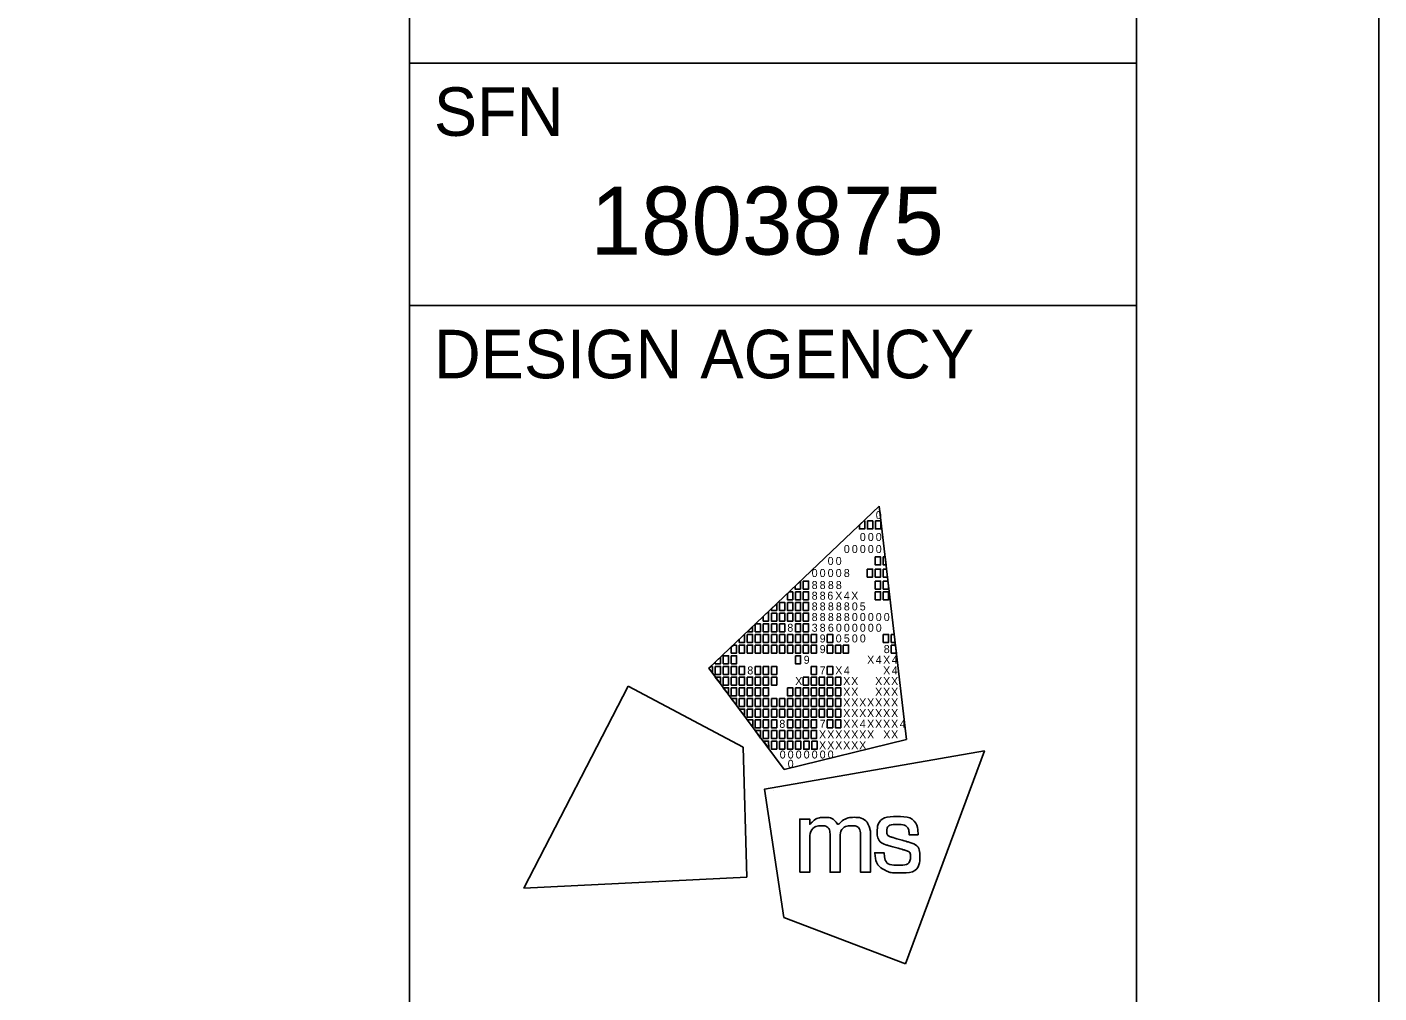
# Model space of a CAD drawing. Extents: x 0 to 34, y 0 to 22.
# Drawn here: x 31.211 to 34, y 3.582 to 5.574 of the extents above; entities that cross this region are included whole.
import ezdxf

# ---------------------------------------------------------------- set-up
doc = ezdxf.new("R2010")
doc.units = 0
for name, color, linetype in [('Default', 7, 'Continuous'), ('SH_Border', 7, 'Continuous'), ('SH_Cut_Line', 7, 'Continuous'), ('SH_Data', 7, 'Continuous')]:
    doc.layers.add(name, color=color, linetype=linetype)

msp = doc.modelspace()

# ---------------------------------------------------------------- linework, layer by layer
at = {"layer": 'Default'}
for p, q in [((32.6176, 4.2519), (32.9688, 4.5861)), ((32.9688, 4.5861), (32.9688, 4.5861)), ((32.9688, 4.5861), (33.0253, 4.1052)), ((32.773, 4.043), (32.6176, 4.2519)), ((33.0253, 4.1052), (32.773, 4.043))]:
    msp.add_line(p, q, dxfattribs=at)
for points in [[(32.9279, 4.5472), (32.9369, 4.5558), (32.939, 4.5558), (32.939, 4.5393), (32.9279, 4.5393)], [(32.9444, 4.5558), (32.9554, 4.5558), (32.9554, 4.5393), (32.9444, 4.5393)], [(32.9609, 4.5558), (32.9719, 4.5558), (32.9719, 4.5393), (32.9609, 4.5393)], [(32.9606, 4.4815), (32.9716, 4.4815), (32.9716, 4.465), (32.9606, 4.465)], [(32.9771, 4.4815), (32.9811, 4.4815), (32.983, 4.465), (32.9771, 4.465)], [(32.9442, 4.4567), (32.9552, 4.4567), (32.9552, 4.4402), (32.9442, 4.4402)], [(32.9606, 4.4567), (32.9716, 4.4567), (32.9716, 4.4402), (32.9606, 4.4402)], [(32.9771, 4.4567), (32.984, 4.4567), (32.9859, 4.4402), (32.9771, 4.4402)], [(32.7954, 4.4211), (32.8064, 4.4316), (32.8064, 4.4154), (32.7954, 4.4154)], [(32.7958, 4.4099), (32.8068, 4.4099), (32.8068, 4.3934), (32.7958, 4.3934)], [(32.8123, 4.4319), (32.8233, 4.4319), (32.8233, 4.4154), (32.8123, 4.4154)], [(32.8123, 4.4099), (32.8233, 4.4099), (32.8233, 4.3934), (32.8123, 4.3934)], [(32.9606, 4.4319), (32.9716, 4.4319), (32.9716, 4.4154), (32.9606, 4.4154)], [(32.9606, 4.4099), (32.9716, 4.4099), (32.9716, 4.3934), (32.9606, 4.3934)], [(32.9771, 4.4319), (32.9869, 4.4319), (32.9881, 4.4218), (32.9881, 4.4154), (32.9771, 4.4154)], [(32.9771, 4.4099), (32.9881, 4.4099), (32.9881, 4.3934), (32.9771, 4.3934)], [(32.7628, 4.3879), (32.7738, 4.3879), (32.7738, 4.3714), (32.7628, 4.3714)], [(32.7793, 4.3879), (32.7903, 4.3879), (32.7903, 4.3714), (32.7793, 4.3714)], [(32.7958, 4.3879), (32.8068, 4.3879), (32.8068, 4.3714), (32.7958, 4.3714)], [(32.8123, 4.3879), (32.8233, 4.3879), (32.8233, 4.3714), (32.8123, 4.3714)], [(32.7463, 4.3659), (32.7573, 4.3659), (32.7573, 4.3494), (32.7463, 4.3494)], [(32.7628, 4.3659), (32.7738, 4.3659), (32.7738, 4.3494), (32.7628, 4.3494)], [(32.7793, 4.3659), (32.7903, 4.3659), (32.7903, 4.3494), (32.7793, 4.3494)], [(32.7958, 4.3659), (32.8068, 4.3659), (32.8068, 4.3494), (32.7958, 4.3494)], [(32.8123, 4.3659), (32.8233, 4.3659), (32.8233, 4.3494), (32.8123, 4.3494)], [(32.7297, 4.3439), (32.7407, 4.3439), (32.7407, 4.3273), (32.7297, 4.3273)], [(32.7463, 4.3439), (32.7573, 4.3439), (32.7573, 4.3273), (32.7463, 4.3273)], [(32.7628, 4.3439), (32.7738, 4.3439), (32.7738, 4.3273), (32.7628, 4.3273)], [(32.7958, 4.3439), (32.8068, 4.3439), (32.8068, 4.3273), (32.7958, 4.3273)], [(32.8123, 4.3439), (32.8233, 4.3439), (32.8233, 4.3273), (32.8123, 4.3273)], [(32.6802, 4.2998), (32.6912, 4.2998), (32.6912, 4.2833), (32.6802, 4.2833)], [(32.6967, 4.3218), (32.7077, 4.3218), (32.7077, 4.3053), (32.6967, 4.3053)], [(32.6967, 4.2998), (32.7077, 4.2998), (32.7077, 4.2833), (32.6967, 4.2833)], [(32.7132, 4.3218), (32.7242, 4.3218), (32.7242, 4.3053), (32.7132, 4.3053)], [(32.7132, 4.2998), (32.7242, 4.2998), (32.7242, 4.2833), (32.7132, 4.2833)], [(32.7297, 4.3218), (32.7407, 4.3218), (32.7407, 4.3053), (32.7297, 4.3053)], [(32.7297, 4.2998), (32.7407, 4.2998), (32.7407, 4.2833), (32.7297, 4.2833)], [(32.7463, 4.3218), (32.7573, 4.3218), (32.7573, 4.3053), (32.7463, 4.3053)], [(32.7463, 4.2998), (32.7573, 4.2998), (32.7573, 4.2833), (32.7463, 4.2833)], [(32.7628, 4.3218), (32.7738, 4.3218), (32.7738, 4.3053), (32.7628, 4.3053)], [(32.7628, 4.2998), (32.7738, 4.2998), (32.7738, 4.2833), (32.7628, 4.2833)], [(32.7793, 4.3218), (32.7903, 4.3218), (32.7903, 4.3053), (32.7793, 4.3053)], [(32.7793, 4.2998), (32.7903, 4.2998), (32.7903, 4.2833), (32.7793, 4.2833)], [(32.7958, 4.3218), (32.8068, 4.3218), (32.8068, 4.3053), (32.7958, 4.3053)], [(32.7958, 4.2998), (32.8068, 4.2998), (32.8068, 4.2833), (32.7958, 4.2833)], [(32.8123, 4.3218), (32.8233, 4.3218), (32.8233, 4.3053), (32.8123, 4.3053)], [(32.8123, 4.2998), (32.8233, 4.2998), (32.8233, 4.2833), (32.8123, 4.2833)], [(32.8288, 4.3218), (32.8398, 4.3218), (32.8398, 4.3053), (32.8288, 4.3053)], [(32.8288, 4.2998), (32.8398, 4.2998), (32.8398, 4.2833), (32.8288, 4.2833)], [(32.8618, 4.3218), (32.8729, 4.3218), (32.8729, 4.3053), (32.8618, 4.3053)], [(32.8618, 4.2998), (32.8729, 4.2998), (32.8729, 4.2833), (32.8618, 4.2833)], [(32.8784, 4.2998), (32.8894, 4.2998), (32.8894, 4.2833), (32.8784, 4.2833)], [(32.8947, 4.2998), (32.9057, 4.2998), (32.9057, 4.2833), (32.8947, 4.2833)], [(32.9771, 4.3218), (32.9881, 4.3218), (32.9881, 4.3053), (32.9771, 4.3053)], [(32.9936, 4.3218), (32.9999, 4.3218), (33.0018, 4.3053), (32.9936, 4.3053)], [(32.9936, 4.2998), (33.0024, 4.2998), (33.0044, 4.2833), (32.9936, 4.2833)], [(32.6472, 4.2778), (32.6582, 4.2778), (32.6582, 4.2613), (32.6472, 4.2613)], [(32.6637, 4.2778), (32.6747, 4.2778), (32.6747, 4.2613), (32.6637, 4.2613)], [(32.7958, 4.2778), (32.8068, 4.2778), (32.8068, 4.2613), (32.7958, 4.2613)], [(32.6307, 4.2558), (32.6417, 4.2558), (32.6417, 4.2393), (32.6307, 4.2393)], [(32.6472, 4.2558), (32.6582, 4.2558), (32.6582, 4.2393), (32.6472, 4.2393)], [(32.6637, 4.2558), (32.6747, 4.2558), (32.6747, 4.2393), (32.6637, 4.2393)], [(32.6802, 4.2558), (32.6912, 4.2558), (32.6912, 4.2393), (32.6802, 4.2393)], [(32.7132, 4.2558), (32.7242, 4.2558), (32.7242, 4.2393), (32.7132, 4.2393)], [(32.7297, 4.2558), (32.7407, 4.2558), (32.7407, 4.2393), (32.7297, 4.2393)], [(32.7463, 4.2558), (32.7573, 4.2558), (32.7573, 4.2393), (32.7463, 4.2393)], [(32.8288, 4.2558), (32.8398, 4.2558), (32.8398, 4.2393), (32.8288, 4.2393)], [(32.8618, 4.2558), (32.8729, 4.2558), (32.8729, 4.2393), (32.8618, 4.2393)], [(32.6307, 4.2338), (32.6417, 4.2338), (32.6417, 4.22)], [(32.6472, 4.2338), (32.6582, 4.2338), (32.6582, 4.2173), (32.6472, 4.2173)], [(32.6637, 4.2338), (32.6747, 4.2338), (32.6747, 4.2173), (32.6637, 4.2173)], [(32.6802, 4.2338), (32.6912, 4.2338), (32.6912, 4.2173), (32.6802, 4.2173)], [(32.6967, 4.2338), (32.7077, 4.2338), (32.7077, 4.2173), (32.6967, 4.2173)], [(32.7132, 4.2338), (32.7242, 4.2338), (32.7242, 4.2173), (32.7132, 4.2173)], [(32.7297, 4.2338), (32.7407, 4.2338), (32.7407, 4.2173), (32.7297, 4.2173)], [(32.7463, 4.2338), (32.7573, 4.2338), (32.7573, 4.2173), (32.7463, 4.2173)], [(32.8123, 4.2338), (32.8233, 4.2338), (32.8233, 4.2173), (32.8123, 4.2173)], [(32.8288, 4.2338), (32.8398, 4.2338), (32.8398, 4.2173), (32.8288, 4.2173)], [(32.8453, 4.2338), (32.8563, 4.2338), (32.8563, 4.2173), (32.8453, 4.2173)], [(32.8618, 4.2338), (32.8729, 4.2338), (32.8729, 4.2173), (32.8618, 4.2173)], [(32.8784, 4.2338), (32.8894, 4.2338), (32.8894, 4.2173), (32.8784, 4.2173)], [(32.6472, 4.2117), (32.6582, 4.2117), (32.6582, 4.198)], [(32.6637, 4.2117), (32.6747, 4.2117), (32.6747, 4.1952), (32.6637, 4.1952)], [(32.6637, 4.1897), (32.6747, 4.1897), (32.6747, 4.176)], [(32.6747, 4.1897), (32.6747, 4.1897), (32.6747, 4.1897)], [(32.6802, 4.2117), (32.6912, 4.2117), (32.6912, 4.1952), (32.6802, 4.1952)], [(32.6802, 4.1897), (32.6912, 4.1897), (32.6912, 4.1732), (32.6802, 4.1732)], [(32.6967, 4.2117), (32.7077, 4.2117), (32.7077, 4.1952), (32.6967, 4.1952)], [(32.6967, 4.1897), (32.7077, 4.1897), (32.7077, 4.1732), (32.6967, 4.1732)], [(32.7132, 4.2117), (32.7242, 4.2117), (32.7242, 4.1952), (32.7132, 4.1952)], [(32.7132, 4.1897), (32.7242, 4.1897), (32.7242, 4.1732), (32.7132, 4.1732)], [(32.7297, 4.2117), (32.7407, 4.2117), (32.7407, 4.1952), (32.7297, 4.1952)], [(32.7297, 4.1897), (32.7407, 4.1897), (32.7407, 4.1732), (32.7297, 4.1732)], [(32.7463, 4.1897), (32.7573, 4.1897), (32.7573, 4.1732), (32.7463, 4.1732)], [(32.7628, 4.1897), (32.7738, 4.1897), (32.7738, 4.1732), (32.7628, 4.1732)], [(32.7793, 4.2117), (32.7903, 4.2117), (32.7903, 4.1952), (32.7793, 4.1952)], [(32.7793, 4.1897), (32.7903, 4.1897), (32.7903, 4.1732), (32.7793, 4.1732)], [(32.7958, 4.2117), (32.8068, 4.2117), (32.8068, 4.1952), (32.7958, 4.1952)], [(32.7958, 4.1897), (32.8068, 4.1897), (32.8068, 4.1732), (32.7958, 4.1732)], [(32.8123, 4.2117), (32.8233, 4.2117), (32.8233, 4.1952), (32.8123, 4.1952)], [(32.8123, 4.1897), (32.8233, 4.1897), (32.8233, 4.1732), (32.8123, 4.1732)], [(32.8288, 4.2117), (32.8398, 4.2117), (32.8398, 4.1952), (32.8288, 4.1952)], [(32.8288, 4.1897), (32.8398, 4.1897), (32.8398, 4.1732), (32.8288, 4.1732)], [(32.8453, 4.2117), (32.8563, 4.2117), (32.8563, 4.1952), (32.8453, 4.1952)], [(32.8453, 4.1897), (32.8563, 4.1897), (32.8563, 4.1732), (32.8453, 4.1732)], [(32.8618, 4.2117), (32.8729, 4.2117), (32.8729, 4.1952), (32.8618, 4.1952)], [(32.8618, 4.1897), (32.8729, 4.1897), (32.8729, 4.1732), (32.8618, 4.1732)], [(32.8784, 4.2117), (32.8894, 4.2117), (32.8894, 4.1952), (32.8784, 4.1952)], [(32.8784, 4.1897), (32.8894, 4.1897), (32.8894, 4.1732), (32.8784, 4.1732)], [(32.6802, 4.1677), (32.6912, 4.1677), (32.6912, 4.154)], [(32.6967, 4.1677), (32.7077, 4.1677), (32.7077, 4.1512), (32.6967, 4.1512)], [(32.7132, 4.1677), (32.7242, 4.1677), (32.7242, 4.1512), (32.7132, 4.1512)], [(32.7297, 4.1677), (32.7407, 4.1677), (32.7407, 4.1512), (32.7297, 4.1512)], [(32.7463, 4.1677), (32.7573, 4.1677), (32.7573, 4.1512), (32.7463, 4.1512)], [(32.7628, 4.1677), (32.7738, 4.1677), (32.7738, 4.1512), (32.7628, 4.1512)], [(32.7793, 4.1677), (32.7903, 4.1677), (32.7903, 4.1512), (32.7793, 4.1512)], [(32.7958, 4.1677), (32.8068, 4.1677), (32.8068, 4.1512), (32.7958, 4.1512)], [(32.8123, 4.1677), (32.8233, 4.1677), (32.8233, 4.1512), (32.8123, 4.1512)], [(32.8288, 4.1677), (32.8398, 4.1677), (32.8398, 4.1512), (32.8288, 4.1512)], [(32.8453, 4.1677), (32.8563, 4.1677), (32.8563, 4.1512), (32.8453, 4.1512)], [(32.8618, 4.1677), (32.8729, 4.1677), (32.8729, 4.1512), (32.8618, 4.1512)], [(32.8784, 4.1677), (32.8894, 4.1677), (32.8894, 4.1512), (32.8784, 4.1512)], [(32.7078, 4.1305), (32.6966, 4.1457), (32.7078, 4.1457)], [(32.7132, 4.1457), (32.7242, 4.1457), (32.7242, 4.1292), (32.7132, 4.1292)], [(32.7297, 4.1457), (32.7407, 4.1457), (32.7407, 4.1292), (32.7297, 4.1292)], [(32.7463, 4.1457), (32.7573, 4.1457), (32.7573, 4.1292), (32.7463, 4.1292)], [(32.7793, 4.1457), (32.7903, 4.1457), (32.7903, 4.1292), (32.7793, 4.1292)], [(32.7958, 4.1457), (32.8068, 4.1457), (32.8068, 4.1292), (32.7958, 4.1292)], [(32.8123, 4.1457), (32.8233, 4.1457), (32.8233, 4.1292), (32.8123, 4.1292)], [(32.8288, 4.1457), (32.8398, 4.1457), (32.8398, 4.1292), (32.8288, 4.1292)], [(32.8618, 4.1457), (32.8729, 4.1457), (32.8729, 4.1292), (32.8618, 4.1292)], [(32.8784, 4.1457), (32.8894, 4.1457), (32.8894, 4.1292), (32.8784, 4.1292)], [(32.724, 4.1082), (32.7132, 4.1237), (32.7242, 4.1237)], [(32.7297, 4.1237), (32.7407, 4.1237), (32.7407, 4.1072), (32.7297, 4.1072)], [(32.7302, 4.1017), (32.7407, 4.1017), (32.7408, 4.0875)], [(32.7463, 4.1237), (32.7573, 4.1237), (32.7573, 4.1072), (32.7463, 4.1072)], [(32.7463, 4.1017), (32.7573, 4.1017), (32.7573, 4.0852), (32.7463, 4.0852)], [(32.7628, 4.1237), (32.7738, 4.1237), (32.7738, 4.1072), (32.7628, 4.1072)], [(32.763, 4.1017), (32.774, 4.1017), (32.774, 4.0852), (32.763, 4.0852)], [(32.7793, 4.1237), (32.7903, 4.1237), (32.7903, 4.1072), (32.7793, 4.1072)], [(32.7794, 4.1017), (32.7904, 4.1017), (32.7904, 4.0852), (32.7794, 4.0852)], [(32.7958, 4.1237), (32.8068, 4.1237), (32.8068, 4.1072), (32.7958, 4.1072)], [(32.7961, 4.1017), (32.8071, 4.1017), (32.8071, 4.0852), (32.7961, 4.0852)], [(32.8123, 4.1237), (32.8233, 4.1237), (32.8233, 4.1072), (32.8123, 4.1072)], [(32.813, 4.1017), (32.824, 4.1017), (32.824, 4.0851), (32.813, 4.0851)], [(32.8288, 4.1237), (32.8398, 4.1237), (32.8398, 4.1072), (32.8288, 4.1072)], [(32.8296, 4.1017), (32.8407, 4.1017), (32.8407, 4.0851), (32.8296, 4.0851)]]:
    msp.add_lwpolyline(points, close=True, dxfattribs=at)
for points in [[(32.7903, 4.4099), (32.7836, 4.4099), (32.7793, 4.4058), (32.7793, 4.3934), (32.7903, 4.3934), (32.7903, 4.4099)], [(32.7573, 4.3849), (32.7463, 4.3744), (32.7463, 4.3714), (32.7573, 4.3714), (32.7573, 4.3849)], [(32.7407, 4.3691), (32.7297, 4.3587), (32.7297, 4.3494), (32.7407, 4.3494), (32.7407, 4.3691)], [(32.7077, 4.3377), (32.6968, 4.3273), (32.7077, 4.3273), (32.7077, 4.3377)], [(32.7242, 4.3439), (32.7142, 4.3439), (32.7132, 4.343), (32.7132, 4.3273), (32.7242, 4.3273), (32.7242, 4.3439)], [(32.6747, 4.2998), (32.6679, 4.2998), (32.6637, 4.2958), (32.6637, 4.2833), (32.6747, 4.2833), (32.6747, 4.2998)], [(32.6912, 4.322), (32.6802, 4.3115), (32.6802, 4.3053), (32.6912, 4.3053), (32.6912, 4.322)], [(32.6417, 4.2749), (32.6307, 4.2644), (32.6307, 4.2613), (32.6417, 4.2613), (32.6417, 4.2749)], [(32.6252, 4.2558), (32.6216, 4.2558), (32.6176, 4.2519), (32.6252, 4.2417), (32.6252, 4.2558)], [(32.4512, 4.2149), (32.2359, 3.7988), (32.6957, 3.8215), (32.6884, 4.0892), (32.4512, 4.2149)], [(33.0229, 3.6422), (33.1859, 4.0814), (32.7324, 4.0029), (32.7722, 3.7381), (33.0229, 3.6422)]]:
    msp.add_lwpolyline(points, dxfattribs=at)
for points in [[(32.8048, 3.8315), (32.8048, 3.8315), (32.8048, 3.9409), (32.8048, 3.9409), (32.8048, 3.9409), (32.8255, 3.9409), (32.8255, 3.9409), (32.8255, 3.9409), (32.8255, 3.9297), (32.8255, 3.9297), (32.8346, 3.9399), (32.8457, 3.9445), (32.8555, 3.9445), (32.8689, 3.9445), (32.8792, 3.9372), (32.8837, 3.9266), (32.8915, 3.9381), (32.905, 3.9446), (32.9166, 3.9446), (32.9325, 3.9446), (32.9451, 3.935), (32.9494, 3.9213), (32.9494, 3.9212), (32.9494, 3.9212), (32.9495, 3.9212), (32.9501, 3.919), (32.9507, 3.9172), (32.9507, 3.9071), (32.9507, 3.9071), (32.9507, 3.8314), (32.9507, 3.8314), (32.9507, 3.8314), (32.9303, 3.8314), (32.9303, 3.8314), (32.9303, 3.8314), (32.9303, 3.9048), (32.9303, 3.9048), (32.9303, 3.9201), (32.9219, 3.9274), (32.9111, 3.9274), (32.8995, 3.9274), (32.888, 3.9171), (32.888, 3.9001), (32.888, 3.9001), (32.888, 3.8315), (32.888, 3.8315), (32.888, 3.8315), (32.8674, 3.8315), (32.8674, 3.8315), (32.8674, 3.8315), (32.8674, 3.9059), (32.8674, 3.9059), (32.8674, 3.9203), (32.8588, 3.9274), (32.8497, 3.9274), (32.8384, 3.9274), (32.8254, 3.917), (32.8254, 3.8962), (32.8254, 3.8962), (32.8254, 3.8315), (32.8254, 3.8315), (32.8254, 3.8315), (32.8048, 3.8315), (32.8048, 3.8315)], [(32.9596, 3.8709), (32.9596, 3.8709), (32.9595, 3.8717), (32.9595, 3.8717), (32.9595, 3.8717), (32.9603, 3.8717), (32.9603, 3.8717), (32.9603, 3.8717), (32.9783, 3.8717), (32.9783, 3.8717), (32.9783, 3.8717), (32.9789, 3.8717), (32.9789, 3.8717), (32.9789, 3.8717), (32.979, 3.871), (32.979, 3.871), (32.9803, 3.8554), (32.9887, 3.846), (33.009, 3.846), (33.0273, 3.846), (33.0333, 3.8554), (33.0333, 3.8631), (33.0333, 3.8732), (33.0256, 3.8758), (33.0175, 3.878), (33.0175, 3.878), (32.987, 3.8867), (32.987, 3.8867), (32.9721, 3.8909), (32.9648, 3.9019), (32.9648, 3.9142), (32.9648, 3.9303), (32.9768, 3.9462), (33.0052, 3.9462), (33.0348, 3.9462), (33.0489, 3.9285), (33.0489, 3.9095), (33.0489, 3.9095), (33.0489, 3.9087), (33.0489, 3.9087), (33.0489, 3.9087), (33.0482, 3.9087), (33.0482, 3.9087), (33.0482, 3.9087), (33.0312, 3.9087), (33.0312, 3.9087), (33.0312, 3.9087), (33.0305, 3.9087), (33.0305, 3.9087), (33.0305, 3.9087), (33.0305, 3.9094), (33.0305, 3.9094), (33.0302, 3.9208), (33.0227, 3.93), (33.0056, 3.93), (32.9891, 3.93), (32.9843, 3.9218), (32.9843, 3.9157), (32.9843, 3.9108), (32.9869, 3.9059), (32.9959, 3.9033), (32.9959, 3.9033), (33.0255, 3.8948), (33.0255, 3.8948), (33.0462, 3.8889), (33.0527, 3.8777), (33.0527, 3.8639), (33.0527, 3.8462), (33.041, 3.8298), (33.0087, 3.8298), (32.9952, 3.8298), (32.9877, 3.8321), (32.9823, 3.8348), (32.9691, 3.8414), (32.961, 3.8536), (32.9596, 3.8709)]]:
    msp.add_open_spline(points, degree=3, dxfattribs=at)
at = {"layer": 'SH_Border'}
for p, q in [((32, 0.5), (32, 21.5)), ((32, 5.5), (33.5, 5.5)), ((32, 5), (33.5, 5))]:
    msp.add_line(p, q, dxfattribs=at)
msp.add_lwpolyline([(1.5, 21.5), (33.5, 21.5), (33.5, 0.5), (1.5, 0.5)], close=True, dxfattribs=at)
at = {"layer": 'SH_Cut_Line'}
msp.add_lwpolyline([(0, 0), (34, 0), (34, 22), (0, 22)], close=True, dxfattribs=at)
at = {"layer": 'SH_Data'}
msp.add_line((32.75, 4), (32.75, 4), dxfattribs=at)

# ---------------------------------------------------------------- texts
at = {"layer": 'Default'}
for s, p in [('0', (32.9617, 4.5597)), ('0', (32.9288, 4.5145)), ('0', (32.9453, 4.5145)), ('0', (32.9617, 4.5145)), ('0', (32.8958, 4.4897)), ('0', (32.9123, 4.4897)), ('0', (32.9288, 4.4897)), ('0', (32.9453, 4.4897)), ('0', (32.9617, 4.4897)), ('0', (32.8625, 4.465)), ('0', (32.8791, 4.465)), ('0', (32.8295, 4.4402)), ('0', (32.846, 4.4402)), ('0', (32.8625, 4.4402)), ('0', (32.8791, 4.4402)), ('8', (32.8958, 4.4402)), ('8', (32.8295, 4.4154)), ('8', (32.8295, 4.3934)), ('8', (32.846, 4.4154)), ('8', (32.846, 4.3934)), ('6', (32.8618, 4.3934)), ('8', (32.8629, 4.4154)), ('X', (32.8781, 4.3934)), ('8', (32.8793, 4.4154)), ('4', (32.8959, 4.3934)), ('X', (32.911, 4.3934)), ('8', (32.8295, 4.3713)), ('8', (32.846, 4.3713)), ('8', (32.8629, 4.3713)), ('8', (32.8794, 4.3713)), ('8', (32.8958, 4.3713)), ('0', (32.9123, 4.3713)), ('5', (32.9287, 4.3713)), ('8', (32.8295, 4.3494)), ('8', (32.846, 4.3494)), ('8', (32.8629, 4.3494)), ('8', (32.8794, 4.3494)), ('8', (32.8958, 4.3494)), ('0', (32.9123, 4.3494)), ('0', (32.9288, 4.3494)), ('0', (32.9453, 4.3494)), ('0', (32.9617, 4.3494)), ('0', (32.9782, 4.3494)), ('8', (32.7793, 4.3273)), ('3', (32.8295, 4.3273)), ('8', (32.846, 4.3273)), ('6', (32.8629, 4.3273)), ('0', (32.8794, 4.3273)), ('0', (32.8958, 4.3273)), ('0', (32.9123, 4.3273)), ('0', (32.9288, 4.3273)), ('0', (32.9453, 4.3273)), ('0', (32.9617, 4.3273)), ('9', (32.846, 4.3053)), ('9', (32.846, 4.2833)), ('0', (32.8791, 4.3053)), ('5', (32.8958, 4.3053)), ('0', (32.9123, 4.3053)), ('0', (32.9288, 4.3053)), ('8', (32.9782, 4.2833)), ('9', (32.813, 4.2613)), ('X', (32.9439, 4.2613)), ('4', (32.9617, 4.2613)), ('X', (32.9769, 4.2613)), ('4', (32.9947, 4.2613)), ('8', (32.6967, 4.2393)), ('7', (32.846, 4.2393)), ('X', (32.8781, 4.2393)), ('4', (32.8959, 4.2393)), ('X', (32.9769, 4.2393)), ('4', (32.9947, 4.2393)), ('X', (32.7955, 4.2173)), ('X', (32.8945, 4.2173)), ('X', (32.911, 4.2173)), ('X', (32.9604, 4.2173)), ('X', (32.9769, 4.2173)), ('X', (32.9934, 4.2173)), ('X', (32.8945, 4.1952)), ('X', (32.8945, 4.1732)), ('X', (32.911, 4.1952)), ('X', (32.911, 4.1732)), ('X', (32.9275, 4.1732)), ('X', (32.9439, 4.1732)), ('X', (32.9604, 4.1952)), ('X', (32.9604, 4.1732)), ('X', (32.9769, 4.1952)), ('X', (32.9769, 4.1732)), ('X', (32.9934, 4.1952)), ('X', (32.9934, 4.1732)), ('X', (32.8945, 4.1512)), ('X', (32.911, 4.1512)), ('X', (32.9275, 4.1512)), ('X', (32.9439, 4.1512)), ('X', (32.9604, 4.1512)), ('X', (32.9769, 4.1512)), ('X', (32.9934, 4.1512)), ('8', (32.7628, 4.1292)), ('7', (32.846, 4.1292)), ('X', (32.8945, 4.1292)), ('X', (32.911, 4.1292)), ('4', (32.9288, 4.1292)), ('X', (32.9439, 4.1292)), ('X', (32.9604, 4.1292)), ('X', (32.9769, 4.1292)), ('X', (32.9934, 4.1292)), ('4', (33.0112, 4.1292)), ('X', (32.8447, 4.1072)), ('X', (32.8447, 4.0851)), ('X', (32.8616, 4.1072)), ('X', (32.8616, 4.0851)), ('X', (32.8781, 4.1072)), ('X', (32.8781, 4.0851)), ('X', (32.8945, 4.1072)), ('X', (32.8945, 4.0851)), ('X', (32.911, 4.1072)), ('X', (32.911, 4.0851)), ('X', (32.9275, 4.1072)), ('X', (32.9275, 4.0851)), ('X', (32.9439, 4.1072)), ('X', (32.9772, 4.1072)), ('X', (32.9934, 4.1072)), ('0', (32.7635, 4.0659)), ('0', (32.78, 4.0659)), ('0', (32.7965, 4.0659)), ('0', (32.813, 4.0659)), ('0', (32.8295, 4.0659)), ('0', (32.846, 4.0659)), ('0', (32.8625, 4.0659)), ('0', (32.78, 4.0467))]:
    msp.add_text(s, height=0.0165, rotation=360, dxfattribs=at).set_placement(p)
at = {"layer": 'SH_Data'}
for s, height, p in [('SFN', 0.1, (32.05, 5.35)), ('1803875', 0.14, (32.3733, 5.105)), ('DESIGN AGENCY', 0.1, (32.05, 4.85))]:
    msp.add_text(s, height=height, dxfattribs=at).set_placement(p)

doc.saveas('drawing.dxf')
